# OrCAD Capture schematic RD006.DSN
size A3
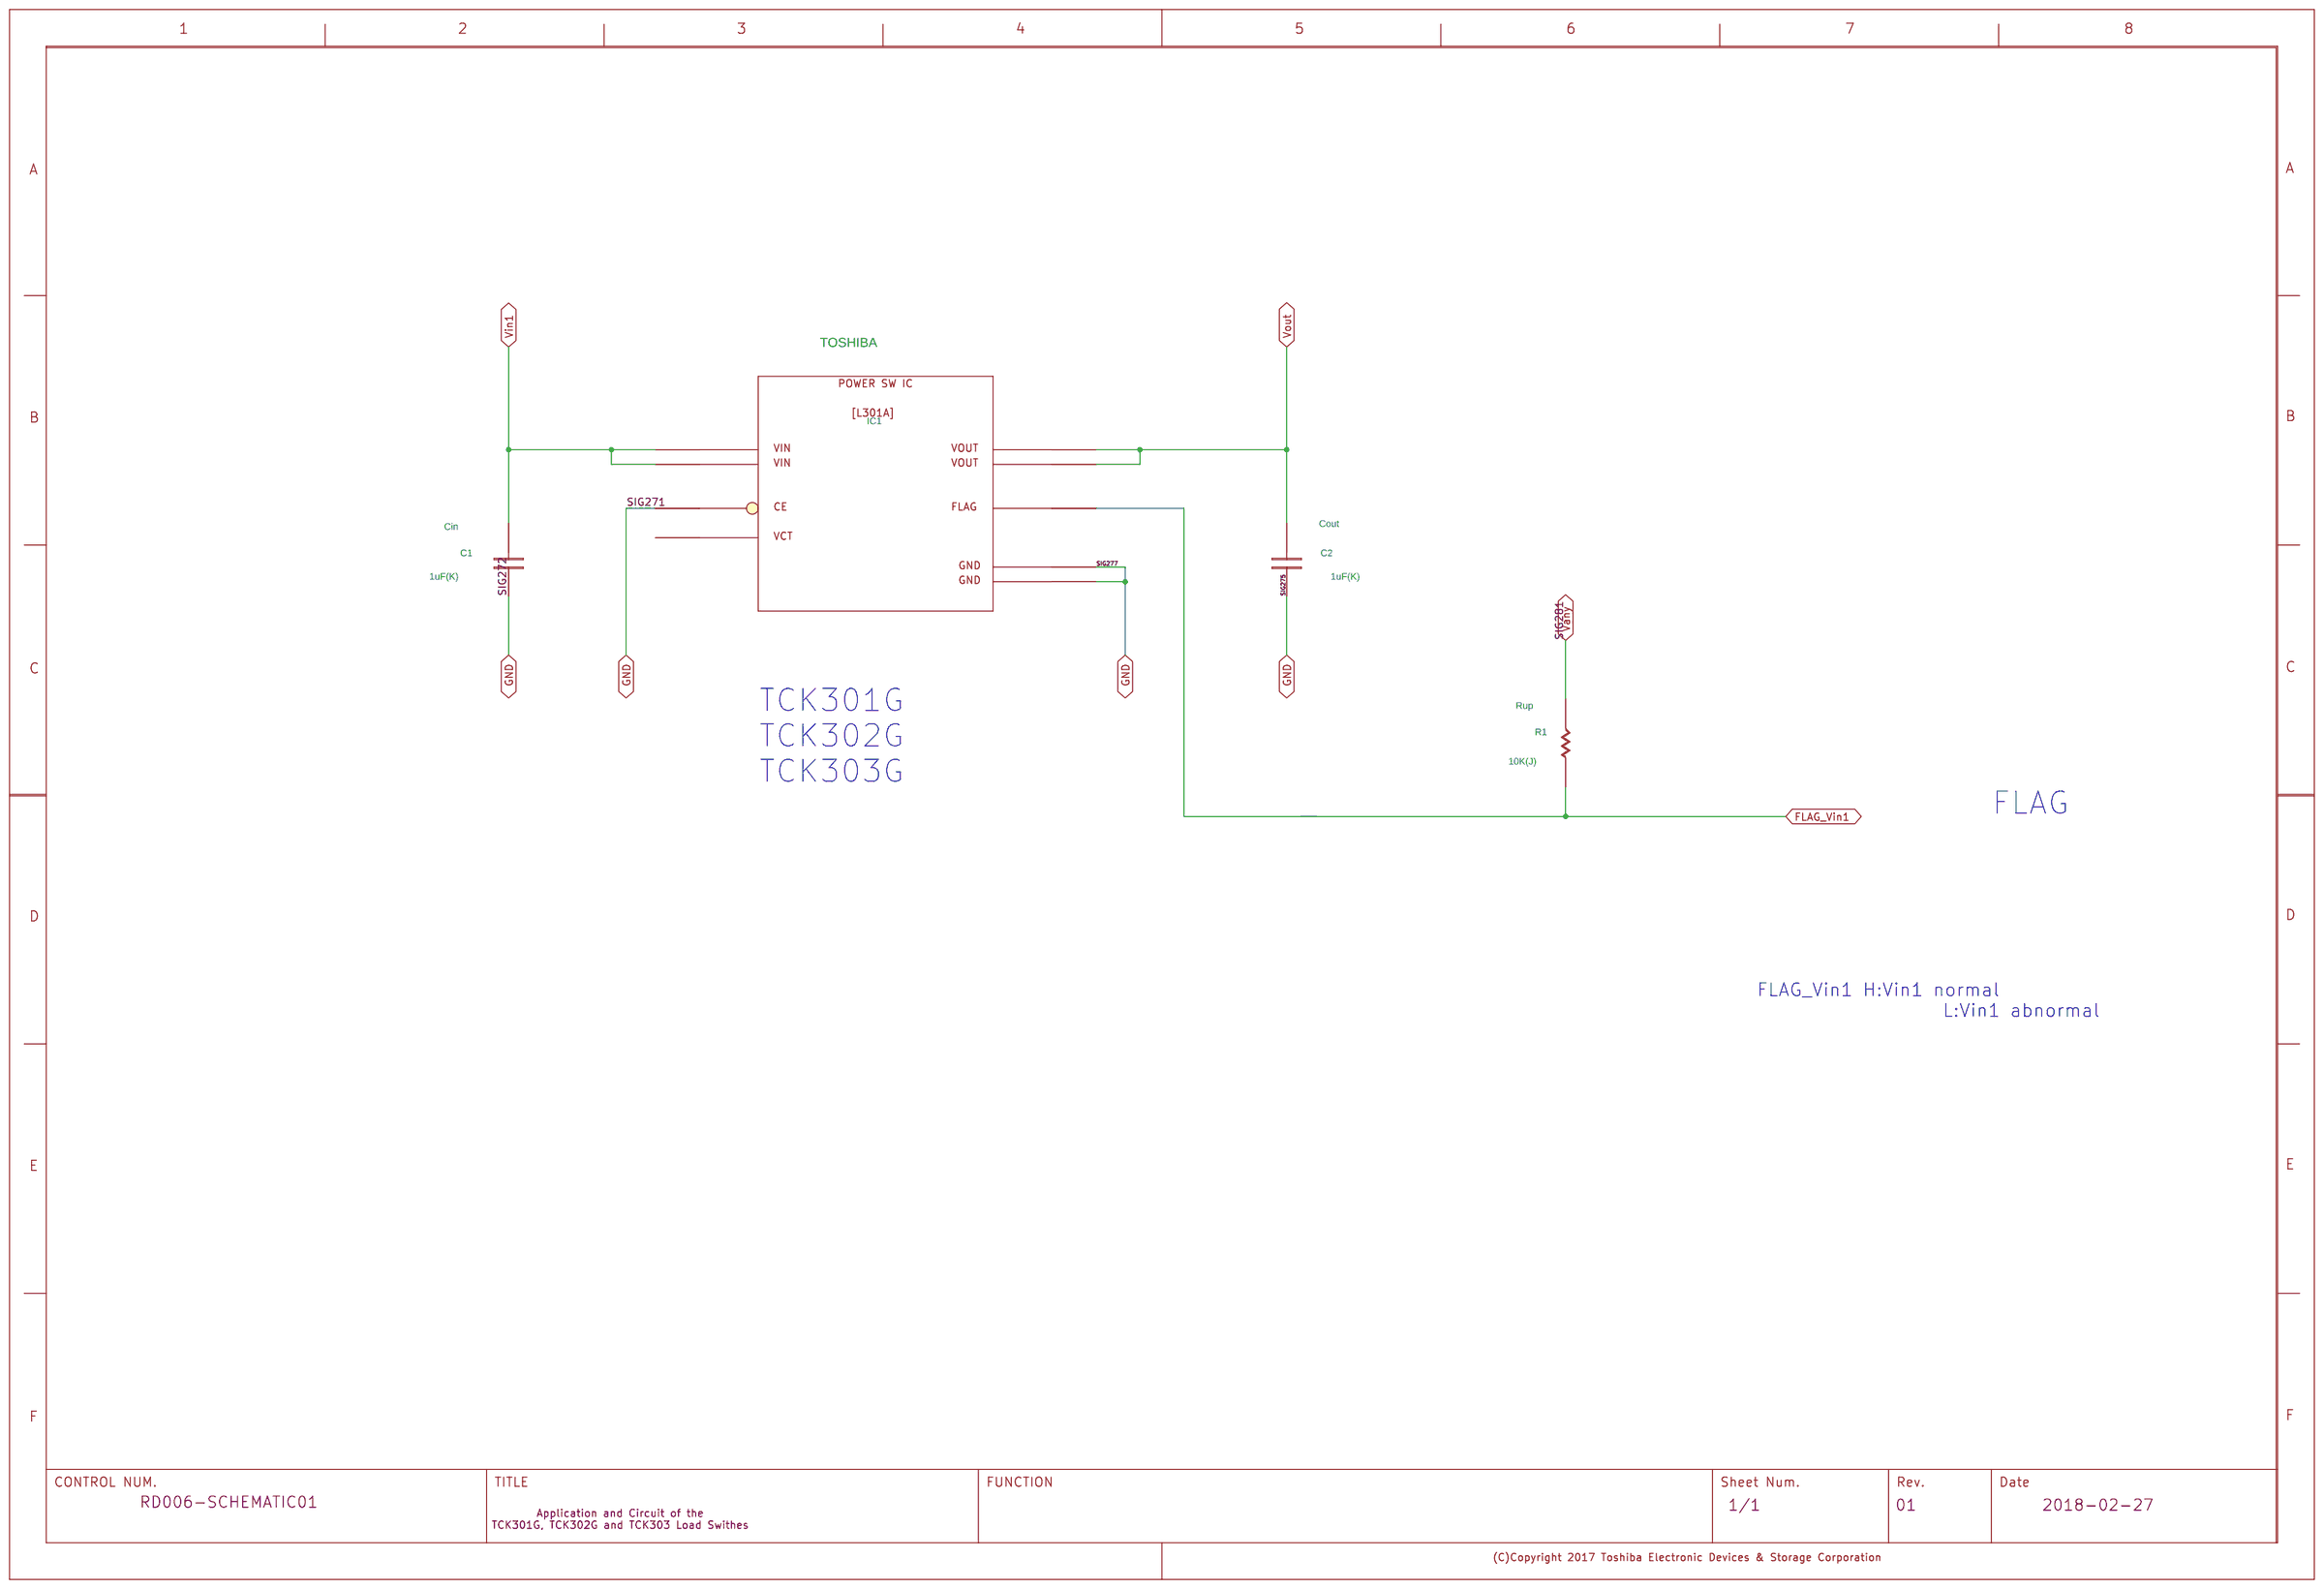
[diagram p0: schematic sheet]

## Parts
C1  C
C2  C
IC1  L301A
R1  R
U?#1  WAKU_DEF100

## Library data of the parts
C1 = C: COMP: PTR_3; COMPONENTTYPE: 4; GCOUNT: 1; MAXGCOUNT: 1; SIZECODESMD: 3216; USERCOMPTEXT1: Cin; VAL1: 1uF(K); VAL2: 50V
C2 = C: COMP: PRT_3; COMPONENTTYPE: 4; GCOUNT: 1; MAXGCOUNT: 1; SIZECODESMD: 3216; USERCOMPTEXT1: Cout; VAL1: 1uF(K); VAL2: 50V
IC1 = L301A: COMP: PRT_1; COMPONENTTYPE: 4; GCOUNT: 1; MAXGCOUNT: 1; OUMEPARTTYPE: IC; USERCOMPTEXT1: TCK301G; USERCOMPTEXT2: TCK302G; USERCOMPTEXT3: TOSHIBA; VAL1: TCK301G; VAL3: TCK301G
R1 = R: COMP: PRT_2; COMPONENTTYPE: 4; GCOUNT: 1; MAXGCOUNT: 1; SIZECODESMD: 1005; USERCOMPTEXT1: Rup; VAL1: 10K(J); VAL2: 63mW
U?#1 = WAKU_DEF100: COMPONENTTYPE: 2; DATE: 2018-02-27; DRAWINGNUMBER: RD006-SCHEMATIC01; FUNCTION: 2-Power monitoring circuit; REVISION: 01; SHEETNUMBER: 1/1; TITLE: Application and Circuit of the / TCK301G, TCK302G and TCK303 Load Swithes; UPDATEDATE: 2018/03/01; UPDATETIME: 12:00:13; UPDATEUSER: f1043010

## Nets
GND: C1.1 C2.1 IC1.A3 IC1.B2 IC1.C2
Vin1: C1.2 IC1.B1 IC1.C1
FLAG_Vin1: IC1.A1 R1.1
Vany: R1.2
Vout: C2.2 IC1.B3 IC1.C3

Not connected (* = marked no-connect by the designer): IC1 A2

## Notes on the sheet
- TCK301G
  TCK302G
  TCK303G
- FLAG
- FLAG_Vin1 H:Vin1 normal
                     L:Vin1 abnormal
